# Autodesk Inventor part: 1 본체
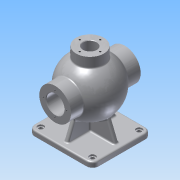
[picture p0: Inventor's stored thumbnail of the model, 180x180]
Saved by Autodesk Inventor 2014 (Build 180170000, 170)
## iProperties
Created: 2017-01
Part Number: 1 본체
Material: Aluminum 6061
Document SubType Name: Modeling
Designer: ksu
Density: 2.71 g/cm^3
Appearance: Aluminum - Flat
Mass: 1509.12 g
Surface Area: 1155.09 cm^2
Volume: 556.87 cm^3
Author: ksu
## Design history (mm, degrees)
sketch "Sketch1"
  geometry: C1 r 31 at (0, 0); 1 further point
  constraints: 1 centre point, 1 coincident
  dimensions: "d1" = 62 diameter of C1
extrude "Extrusion1" new body sketch "Sketch1" stored distance "d2" = 136; taper "d3" = 0 deg
workplane "Work Plane1"
sketch "Sketch2"
  geometry: L1 (-53, 0)-(53, 0); C1 r 31 at (0, 0) reference; A1 r 53 centre (0, 0) between (53, 0) and (-53, 0); 1 further point
  constraints: 2 end point, 2 point on circle, 1 centre point, 1 coincident, 1 horizontal
  dimensions: "d5" = 106 diameter of A1
revolve "Revolution1" sketch "Sketch2" stored, may be unused: angle "d6" = 90 deg
workplane "Work Plane2"
sketch "Sketch3"
  geometry: C1 r 27 at (0, 0); 1 further point
  constraints: 1 centre point, 1 coincident
  dimensions: "d8" = 54 diameter of C1
extrude "Extrusion2" join sketch "Sketch3" distance "d9" = 60; taper "d10" = 0 deg
sketch "Sketch4"
  geometry: L1 (-31, 42.988)-(-31, 68) reference; L2 (-31, 68)-(31, 68) reference; L3 (31, 68)-(31, 42.988) reference; L4 (45.607, 27)-(65, 27) reference; L5 (65, 27)-(65, -27) reference; L6 (65, -27)-(45.607, -27) reference; L7 (31, -42.988)-(31, -68) reference; L8 (31, -68)-(-31, -68) reference; L9 (-31, -68)-(-31, -42.988) reference; L10 (0, 68)-(17.5, 68); L11 (17.5, 68)-(17.5, 39.278); L12 (17.5, -39.278)-(17.5, -68); L13 (0, 68)-(0, -68); L14 (17.5, -68)-(0, -68); A1 r 53 centre (0, 0) between (-31, 42.988) and (-31, -42.988) reference; A2 r 53 centre (0, 0) between (45.607, 27) and (31, 42.988) reference; A3 r 53 centre (0, 0) between (31, -42.988) and (45.607, -27) reference; A4 r 43 centre (0, 0) between (17.5, -39.278) and (17.5, 39.278); 1 further point
  constraints: 10 end point, 2 collinear, 2 midpoint, 2 point on circle, 2 point on line, 1 centre point, 1 coincident, 1 perpendicular
  dimensions: "d11" = 17.5 distance of L10.start L10.end; "d12" = 86 diameter of A4
revolve "Revolution2" sketch "Sketch4" stored, may be unused: angle "d14" = 90 deg
sketch "Sketch5"
  geometry: C1 r 27 at (0, 0) reference; C2 r 13 at (0, 0)
  constraints: 1 centre point, 1 coincident
  dimensions: "d15" = 26 diameter of C2
extrude "Extrusion3" cut sketch "Sketch5" distance "d16" = 60; taper "d17" = 0 deg
workplane "Work Plane3"
sketch "Sketch6"
  geometry: L1 (-62.5, 57.5)-(62.5, 57.5); L2 (62.5, 57.5)-(62.5, -57.5); L3 (62.5, -57.5)-(-62.5, -57.5); L4 (-62.5, -57.5)-(-62.5, 57.5); L5 (-62.5, 57.5)-(62.5, -57.5); L6 (62.5, 57.5)-(-62.5, -57.5); 1 further point
  constraints: 12 end point, 2 midpoint, 2 parallel, 1 horizontal, 1 perpendicular
  dimensions: "d19" = 125 distance of L2.end L3.end; "d20" = 115 distance of L1.end L2.end
extrude "Extrusion4" join sketch "Sketch6" distance "d21" = 10; taper "d22" = 0 deg
sketch "Sketch7"
  geometry: L1 (-27, 45.607)-(-27, 65) reference; L2 (-27, 65)-(-13, 65) reference; L3 (-13, 65)-(-13, 40.988) reference; L4 (13, 40.988)-(13, 65) reference; L5 (13, 65)-(27, 65) reference; L6 (27, 65)-(27, 45.607) reference; L7 (62.5, -75)-(62.5, -85) reference; L8 (62.5, -85)-(-62.5, -85) reference; L9 (-62.5, -85)-(-62.5, -75) reference; L10 (-62.5, -75)-(62.5, -75) reference; L11 (-62.5, -75)-(-52.5, -75); L12 (-52.5, -75)-(-35.888, -33.885); L13 (62.5, -75)-(52.5, -75); L14 (52.5, -75)-(35.888, -33.885); L15 (-52.5, -75)-(-52.5, -44.76); A1 r 43 centre (0, 0) between (-13, 40.988) and (13, 40.988) reference; A2 r 53 centre (0, 0) between (-27, 45.607) and (27, 45.607) reference; A3 r 49.357 centre (0, 0) between (-35.888, -33.885) and (35.888, -33.885); 1 further point
  constraints: 10 end point, 2 point on circle, 2 point on line, 1 centre point, 1 coincident, 1 perpendicular
  dimensions: "d23" = 10 distance of L9.end L11.end; "d24" = 10 distance of L7.start L13.end; "d27" = 22 deg angle of L15 L12
extrude "Extrusion5" join sketch "Sketch7" stored distance "d29" = 8; taper "d30" = 0 deg
sketch "Sketch8"
  geometry: L1 (-17.5, -39.278)-(-17.5, -68) reference; L2 (-17.5, -68)-(-31, -68) reference; L3 (-31, -68)-(-31, -42.988) reference; L4 (-52.849, -4)-(-75, -4) reference; L5 (-75, -4)-(-75, -57.5) reference; L6 (-75, -57.5)-(-85, -57.5) reference; L7 (-85, -57.5)-(-85, 57.5) reference; L8 (-85, 57.5)-(-75, 57.5) reference; L9 (-75, 57.5)-(-75, 4) reference; L10 (-75, 4)-(-52.849, 4) reference; L11 (-31, 42.988)-(-31, 68) reference; L12 (-31, 68)-(-17.5, 68) reference; L13 (-17.5, 68)-(-17.5, 39.278) reference; L14 (45.607, 27)-(65, 27) reference; L15 (65, 27)-(65, 13) reference; L16 (65, 13)-(40.988, 13) reference; L17 (17.5, 39.278)-(17.5, 68) reference; L18 (17.5, 68)-(31, 68) reference; L19 (31, 68)-(31, 42.988) reference; L20 (65, -27)-(45.607, -27) reference; L21 (31, -42.988)-(31, -68) reference; L22 (31, -68)-(17.5, -68) reference; L23 (17.5, -68)-(17.5, -39.278) reference; L24 (40.988, -13)-(65, -13) reference; L25 (65, -13)-(65, -27) reference; L26 (-75, 57.5)-(-75, 47.5); L27 (-75, -57.5)-(-75, -47.5); L28 (-75, 47.5)-(-38.421, 32.721); L29 (-75, -47.5)-(-38.421, -32.721); A1 r 53 centre (0, 0) between (-52.849, -4) and (-31, -42.988) reference; A2 r 53 centre (0, 0) between (-31, 42.988) and (-52.849, 4) reference; A3 r 43 centre (0, 0) between (-17.5, 39.278) and (-17.5, -39.278) reference; A4 r 43 centre (0, 0) between (40.988, 13) and (17.5, 39.278) reference; A5 r 53 centre (0, 0) between (45.607, 27) and (31, 42.988) reference; A6 r 53 centre (0, 0) between (31, -42.988) and (45.607, -27) reference; A7 r 43 centre (0, 0) between (17.5, -39.278) and (40.988, -13) reference; A8 r 50.466 centre (0, 0) between (-38.421, 32.721) and (-38.421, -32.721); 1 further point
  constraints: 8 end point, 2 point on circle, 2 point on line, 1 centre point, 1 coincident
  dimensions: "d31" = 10 distance of L8.end L26.end; "d32" = 10 distance of L5.end L27.end
extrude "Extrusion6" join sketch "Sketch8" stored distance "d35" = 8; taper "d36" = 0 deg
sketch "Sketch9"
  geometry: L1 (62.5, 57.5)-(-62.5, 57.5) reference; L2 (-62.5, 57.5)-(-50.5, 57.5); L3 (62.5, 57.5)-(50.5, 57.5); L4 (-50.5, 57.5)-(-50.5, 45.5); L5 (50.5, 57.5)-(50.5, 45.5); L6 (0, 0)-(-40.261, 0); 4 further points
  constraints: 10 end point, 2 coincident, 2 perpendicular, 2 point on line, 2 symmetric about line, 1 parallel
  dimensions: "d37" = 12 distance of L1.end L2.end; "d38" = 12 distance of L1.start L3.end; "d40" = 12 distance of L2.end L4.end; "d41" = 12 distance of L3.end L5.end
hole "Hole1" sketch "Sketch9" at (-50.5, 45.5), (50.5, 45.5), (-50.5, -45.5), (50.5, -45.5) diameter "d42" = 8; stored, may be unused: countersink angle "d46" = 90 deg, drill point angle "d48" = 118 deg; dims "d43" = 6, "d44" = 12, "d45" = 3, "d47" = 8
sketch "Sketch10"
  geometry: C1 r 31 at (0, 0) reference; A1 r 22.5 centre (0, 0) between (0, 22.5) and (-22.5, 0); 2 further points
  constraints: 4 point on circle, 1 centre point, 1 coincident
  dimensions: "d49" = 45 diameter of A1
hole "Hole2" sketch "Sketch10" at (0, 22.5), (-22.5, 0), (0, -22.5), (22.5, 0) diameter "d50" = 3.459; stored, may be unused: countersink angle "d54" = 90 deg, drill point angle "d56" = 118 deg; dims "d51" = 12, "d52" = 4, "d53" = 2, "d55" = 15
sketch "Sketch11"
  geometry: C1 r 31 at (0, 0) reference; A1 r 24 centre (0, 0) between (0, 24) and (-24, 0); 2 further points
  constraints: 4 point on circle, 1 centre point, 1 coincident
  dimensions: "d57" = 48 diameter of A1
hole "Hole3" sketch "Sketch11" at (0, 24), (-24, 0), (0, -24), (24, 0) diameter "d58" = 3.459; stored, may be unused: countersink angle "d62" = 90 deg, drill point angle "d64" = 118 deg; dims "d59" = 16, "d60" = 4, "d61" = 2, "d63" = 19
sketch "Sketch12"
  geometry: L1 (-17.5, -39.278)-(-17.5, -68) reference; L2 (-17.5, -68)-(-22.271, -68) reference; L3 (-22.271, -68)-(-22.271, -49) reference; L4 (-22.271, -49)-(-24, -47.961) reference; L5 (-24, -47.961)-(-25.73, -49) reference; L6 (-25.73, -49)-(-25.73, -68) reference; L7 (-25.73, -68)-(-31, -68) reference; L8 (-31, -68)-(-31, -42.988) reference; L9 (-40.891, -33.719)-(-75, -47.5) reference; L10 (-75, -47.5)-(-75, -57.5) reference; L11 (-75, -57.5)-(-85, -57.5) reference; L12 (-85, -57.5)-(-85, 57.5) reference; L13 (-85, 57.5)-(-75, 57.5) reference; L14 (-75, 57.5)-(-75, 47.5) reference; L15 (-75, 47.5)-(-40.891, 33.719) reference; L16 (-31, 42.988)-(-31, 68) reference; L17 (-31, 68)-(-24.23, 68) reference; L18 (-24.23, 68)-(-24.23, 53) reference; L19 (-24.23, 53)-(-22.5, 51.961) reference; L20 (-22.5, 51.961)-(-20.77, 53) reference; L21 (-20.77, 53)-(-20.77, 68) reference; L22 (-20.77, 68)-(-17.5, 68) reference; L23 (-17.5, 68)-(-17.5, 39.278) reference; L24 (45.607, 27)-(65, 27) reference; L25 (65, 27)-(65, 13) reference; L26 (65, 13)-(40.988, 13) reference; L27 (17.5, 39.278)-(17.5, 68) reference; L28 (17.5, 68)-(20.77, 68) reference; L29 (20.77, 68)-(20.77, 53) reference; L30 (20.77, 53)-(22.5, 51.961) reference; L31 (22.5, 51.961)-(24.23, 53) reference; L32 (24.23, 53)-(24.23, 68) reference; L33 (24.23, 68)-(31, 68) reference; L34 (31, 68)-(31, 42.988) reference; L35 (65, -27)-(45.607, -27) reference; L36 (31, -42.988)-(31, -68) reference; L37 (31, -68)-(25.73, -68) reference; L38 (25.73, -68)-(25.73, -49) reference; L39 (25.73, -49)-(24, -47.961) reference; L40 (24, -47.961)-(22.271, -49) reference; L41 (22.271, -49)-(22.271, -68) reference; L42 (22.271, -68)-(17.5, -68) reference; L43 (17.5, -68)-(17.5, -39.278) reference; L44 (40.988, -13)-(65, -13) reference; L45 (65, -13)-(65, -27) reference; L46 (-17.5, -68)-(-17.5, -52); L47 (0, -52)-(-18.5, -52); L48 (-18.5, -52)-(-18.5, -50.25); L49 (-18.5, -50.25)-(0, -50.25); L50 (0, -50.25)-(0, -52); A1 r 53 centre (0, 0) between (-40.891, -33.719) and (-31, -42.988) reference; A2 r 53 centre (0, 0) between (-31, 42.988) and (-40.891, 33.719) reference; A3 r 43 centre (0, 0) between (-17.5, 39.278) and (-17.5, -39.278) reference; A4 r 43 centre (0, 0) between (40.988, 13) and (17.5, 39.278) reference; A5 r 53 centre (0, 0) between (45.607, 27) and (31, 42.988) reference; A6 r 53 centre (0, 0) between (31, -42.988) and (45.607, -27) reference; A7 r 43 centre (0, 0) between (17.5, -39.278) and (40.988, -13) reference; 1 further point
  constraints: 10 end point, 3 perpendicular, 1 parallel, 1 point on line
  dimensions: "d66" = 18.5 distance of L47.start L47.end; "d67" = 1.75 distance of L47.end L48.end
revolve "Revolution3" sketch "Sketch12" stored, may be unused: angle "d68" = 90 deg
chamfer "Chamfer1" distance "d69" = 1; stored, may be unused: second distance "d70" = 2, angle "d71" = 45 deg
chamfer "Chamfer2" distance "d72" = 1; stored, may be unused: second distance "d73" = 2, angle "d74" = 45 deg
chamfer "Chamfer3" distance "d75" = 1; stored, may be unused: second distance "d76" = 2, angle "d77" = 45 deg
fillet "Fillet1" dims "d78" = 3
fillet "Fillet2" dims "d79" = 3
fillet "Fillet3" dims "d80" = 12
fillet "Fillet4" dims "d81" = 3
fillet "Fillet5" dims "d82" = 3
fillet "Fillet6" dims "d83" = 3
fillet "Fillet7" dims "d84" = 3
workplane "Work Plane4"
sketch "Sketch13"
  geometry: L1 (75.042, -45.5)-(75.042, 45.5) reference; L2 (85, -52.831)-(78, -52.831) reference; L3 (85, 52.831)-(85, -52.831) reference; L4 (78, 52.831)-(85, 52.831) reference; L5 (-65, -27)-(-65, 27) reference; L6 (-65, -27)-(-65, 27) reference; L7 (-47.286, -27)-(-47.286, 27) reference; L8 (-65, 27)-(-47.286, 27) reference; L9 (-297.548, -49.638)-(-297.548, 49.638); L10 (-297.548, 49.638)-(187.548, 49.638); L11 (187.548, 49.638)-(187.548, -49.638); L12 (187.548, -49.638)-(-297.548, -49.638); 1 further point
  constraints: 4 other
emboss "Emboss1" sketch "Sketch13" dims "d87" = 0.5, "d88" = 0
sketch "Sketch14"
  geometry: C1 r 14 at (0, 0) reference; A1 r 20 centre (0, 0) between (0, 20) and (-20, 0); 2 further points
  constraints: 4 point on circle, 1 centre point, 1 coincident
  dimensions: "d89" = 40 diameter of A1
hole "Hole4" sketch "Sketch14" at (0, 20), (-20, 0), (0, -20), (20, 0) diameter "d90" = 3.459; stored, may be unused: countersink angle "d94" = 90 deg, drill point angle "d96" = 118 deg; dims "d91" = 9, "d92" = 4, "d93" = 2, "d95" = 11
body "Solid1"
node "Projected Loop1"
node "Project Cut Edges1"
node "Project Cut Edges2"
node "Project Cut Edges3"
node "Project Cut Edges4"
node "Project Cut Edges5"
node "Project Cut Edges6"
other parameters: "d4" = -68, "d7" = 65, "d18" = -85
